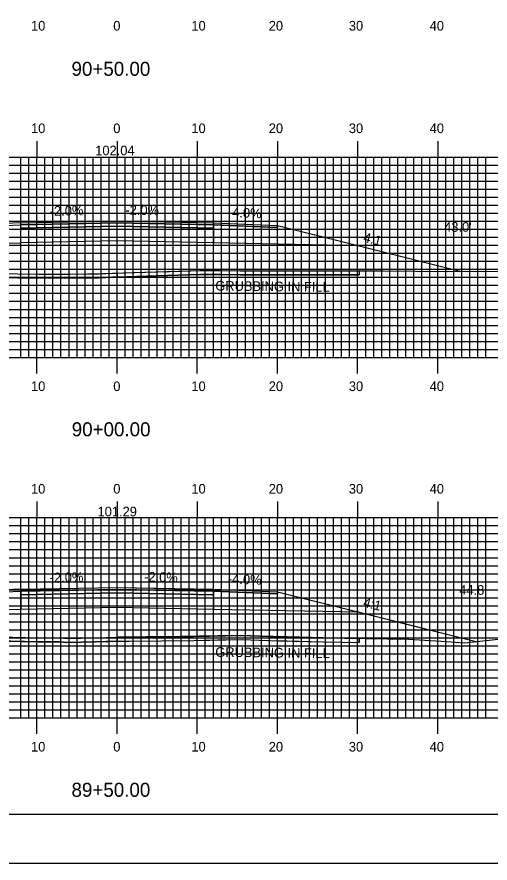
# Model space of a CAD drawing. Extents: x 1764546 to 1764889, y 442591 to 442811.
# Drawn here: x 1764698.8 to 1764757.9, y 442590.5 to 442696.2 of the extents above; entities that cross this region are included whole.
import ezdxf

# ---------------------------------------------------------------- set-up
doc = ezdxf.new("R2010")
doc.units = 0
for name, color, linetype in [('ANNOTATION', 7, 'Continuous'), ('BORDER', 7, 'Continuous'), ('D_Roadway_Centerline', 7, 'Continuous'), ('D_Roadway_Centerline_Text', 7, 'Continuous'), ('D_Roadway_Edge_Shoulder', 7, 'Continuous'), ('D_Roadway_Edge_TW', 7, 'Continuous'), ('D_Roadway_Pavement', 7, 'Continuous'), ('D_Roadway_SlopeLines', 7, 'Continuous'), ('D_Roadway_SubGrade', 7, 'Continuous'), ('D_Text_Standard', 7, 'Continuous'), ('GRUBBING IN FILL', 7, 'Continuous'), ('H_V ANNOTATION', 7, 'Continuous'), ('MAJOR', 7, 'Continuous'), ('MINOR', 7, 'Continuous'), ('PLOT BOUNDARY', 7, 'Continuous'), ('S_Roadway_Centerline', 7, 'Continuous')]:
    doc.layers.add(name, color=color, linetype=linetype)

msp = doc.modelspace()

# ---------------------------------------------------------------- linework, layer by layer
at = {"layer": 'ANNOTATION'}
msp.add_line((1764681.17, 442667.6), (1764699.34, 442667.97), dxfattribs=at)
at = {"layer": 'BORDER'}
msp.add_lwpolyline([(1764561.74, 442596.67), (1764881.74, 442596.67), (1764881.74, 442806.67), (1764561.74, 442806.67)], close=True, dxfattribs=at)
at = {"layer": 'D_Roadway_Centerline'}
msp.add_lwpolyline([(1764671.18, 442619.35), (1764675.92, 442620.54), (1764681.17, 442621.85), (1764681.18, 442621.85), (1764689.31, 442623.89), (1764691.35, 442624.4), (1764691.35, 442624.4), (1764693.28, 442624.47), (1764699.34, 442624.72), (1764699.34, 442624.72), (1764711.34, 442624.96), (1764722.68, 442624.73), (1764723.34, 442624.72), (1764731.34, 442624.4), (1764741.52, 442621.85), (1764741.52, 442621.85), (1764743.34, 442621.4), (1764749.46, 442619.87), (1764756.1, 442618.21)], dxfattribs=at)
at = {"layer": 'D_Roadway_Edge_Shoulder'}
for points in [[(1764699.34, 442670.47), (1764691.35, 442670.15), (1764691.35, 442669.9), (1764699.34, 442670.22)], [(1764723.34, 442670.47), (1764731.35, 442670.15), (1764731.35, 442669.9), (1764723.34, 442670.22)], [(1764699.34, 442624.72), (1764691.35, 442624.4), (1764691.35, 442624.15), (1764699.34, 442624.47)], [(1764723.34, 442624.72), (1764731.34, 442624.4), (1764731.34, 442624.15), (1764723.34, 442624.47)]]:
    msp.add_lwpolyline(points, close=True, dxfattribs=at)
at = {"layer": 'D_Roadway_Edge_TW'}
for points in [[(1764699.34, 442670.22), (1764699.34, 442670.47), (1764711.34, 442670.71), (1764723.34, 442670.47), (1764723.34, 442670.22), (1764711.34, 442670.46)], [(1764723.34, 442670.47), (1764723.34, 442670.47), (1764723.34, 442670.22), (1764723.34, 442670.22)], [(1764699.34, 442624.47), (1764699.34, 442624.72), (1764711.34, 442624.96), (1764723.34, 442624.72), (1764723.34, 442624.47), (1764711.34, 442624.71)], [(1764723.34, 442624.72), (1764723.34, 442624.72), (1764723.34, 442624.47), (1764723.34, 442624.47)]]:
    msp.add_lwpolyline(points, close=True, dxfattribs=at)
at = {"layer": 'D_Roadway_Pavement'}
for points in [[(1764699.34, 442669.8), (1764699.34, 442670.22), (1764711.34, 442670.46), (1764723.34, 442670.22), (1764723.34, 442669.8), (1764711.34, 442670.04)], [(1764723.34, 442670.22), (1764723.34, 442670.22), (1764723.34, 442669.8), (1764723.34, 442669.8)], [(1764699.34, 442624.05), (1764699.34, 442624.47), (1764711.34, 442624.71), (1764723.34, 442624.47), (1764723.34, 442624.05), (1764711.34, 442624.29)], [(1764723.34, 442624.47), (1764723.34, 442624.47), (1764723.34, 442624.05), (1764723.34, 442624.05)]]:
    msp.add_lwpolyline(points, close=True, dxfattribs=at)
for points in [[(1764723.34, 442670.22), (1764723.34, 442669.8)], [(1764723.34, 442670.22), (1764723.34, 442669.8)], [(1764723.34, 442670.22), (1764723.34, 442669.8)], [(1764723.34, 442624.47), (1764723.34, 442624.05)], [(1764723.34, 442624.47), (1764723.34, 442624.05)], [(1764723.34, 442624.47), (1764723.34, 442624.05)]]:
    msp.add_lwpolyline(points, dxfattribs=at)
at = {"layer": 'D_Roadway_SlopeLines'}
for points in [[(1764731.35, 442670.15), (1764741.52, 442667.6), (1764743.34, 442667.15), (1764754.3, 442664.41)], [(1764731.34, 442624.4), (1764741.52, 442621.85), (1764743.34, 442621.4), (1764756.1, 442618.21)]]:
    msp.add_lwpolyline(points, dxfattribs=at)
at = {"layer": 'D_Roadway_SubGrade'}
for points in [[(1764723.34, 442669.8), (1764723.34, 442670.22), (1764731.35, 442669.9), (1764731.35, 442670.15), (1764741.52, 442667.6), (1764723.34, 442667.97)], [(1764699.34, 442667.97), (1764699.34, 442669.8), (1764711.34, 442670.04), (1764723.34, 442669.8), (1764723.34, 442667.97), (1764711.34, 442668.21)], [(1764723.34, 442669.8), (1764723.34, 442669.8), (1764723.34, 442667.97), (1764723.34, 442667.97)], [(1764691.35, 442624.15), (1764699.34, 442624.47), (1764699.34, 442624.05), (1764699.34, 442622.22), (1764681.17, 442621.85), (1764691.35, 442624.4)], [(1764699.34, 442622.22), (1764699.34, 442624.05), (1764711.34, 442624.29), (1764723.34, 442624.05), (1764723.34, 442622.22), (1764711.34, 442622.46)], [(1764723.34, 442624.05), (1764723.34, 442624.47), (1764731.34, 442624.15), (1764731.34, 442624.4), (1764741.52, 442621.85), (1764723.34, 442622.22)], [(1764723.34, 442624.05), (1764723.34, 442624.05), (1764723.34, 442622.22), (1764723.34, 442622.22)]]:
    msp.add_lwpolyline(points, close=True, dxfattribs=at)
at = {"layer": 'GRUBBING IN FILL'}
for p, q in [((1764741.52, 442664.49), (1764741.52, 442663.99)), ((1764741.52, 442618.58), (1764741.52, 442618.08))]:
    msp.add_line(p, q, dxfattribs=at)
for points in [[(1764681.17, 442664.12), (1764685.29, 442663.94), (1764690.36, 442663.79), (1764691.23, 442663.94), (1764693, 442663.68), (1764695.53, 442663.67), (1764696.92, 442663.65), (1764698.9, 442663.62), (1764702.85, 442663.55), (1764707.64, 442663.59), (1764708.26, 442663.58), (1764710.77, 442663.67), (1764721.72, 442664.02), (1764726.7, 442663.99), (1764734.7, 442663.98), (1764741.52, 442663.99)], [(1764696.23, 442664.16), (1764698.91, 442664.12), (1764701.59, 442664.07), (1764702.85, 442664.05), (1764705.25, 442664.07), (1764707.64, 442664.09), (1764708.61, 442664.1), (1764709.5, 442664.13), (1764710.75, 442664.17), (1764711.34, 442664.19), (1764711.34, 442663.69), (1764710.77, 442663.67), (1764710.2, 442663.65), (1764706.07, 442663.57), (1764704.31, 442663.56), (1764702.85, 442663.55), (1764700.88, 442663.58), (1764697.91, 442663.63)], [(1764696.23, 442664.16), (1764698.91, 442664.12), (1764701.59, 442664.07), (1764702.85, 442664.05), (1764705.25, 442664.07), (1764707.64, 442664.09), (1764708.61, 442664.1), (1764709.5, 442664.13), (1764710.75, 442664.17), (1764711.34, 442664.19), (1764711.34, 442663.69), (1764710.77, 442663.67), (1764710.2, 442663.65), (1764706.07, 442663.57), (1764704.31, 442663.56), (1764702.85, 442663.55), (1764700.88, 442663.58), (1764697.91, 442663.63)], [(1764681.17, 442618.42), (1764692.84, 442618.36), (1764695.07, 442618.31), (1764701.49, 442618.17), (1764704.16, 442618.17), (1764705.07, 442618.09), (1764712.16, 442618.26), (1764712.83, 442618.24), (1764720.89, 442618.35), (1764726.89, 442618.46), (1764731.25, 442618.3), (1764732.55, 442618.27), (1764737.02, 442618.15), (1764741.52, 442618.08)]]:
    msp.add_lwpolyline(points, dxfattribs=at)
for points in [[(1764711.34, 442664.19), (1764713.27, 442664.25), (1764716.33, 442664.35), (1764719.39, 442664.45), (1764721.71, 442664.52), (1764724.21, 442664.51), (1764726.7, 442664.49), (1764730.16, 442664.48), (1764732.5, 442664.48), (1764734.7, 442664.48), (1764739.6, 442664.48), (1764741.52, 442664.49), (1764741.52, 442663.99), (1764738.11, 442663.98), (1764734.7, 442663.98), (1764730.7, 442663.98), (1764726.7, 442663.99), (1764724.21, 442664.01), (1764721.72, 442664.02), (1764716.24, 442663.85), (1764711.34, 442663.69)], [(1764711.34, 442664.19), (1764713.27, 442664.25), (1764716.33, 442664.35), (1764719.39, 442664.45), (1764721.71, 442664.52), (1764724.21, 442664.51), (1764726.7, 442664.49), (1764730.16, 442664.48), (1764732.5, 442664.48), (1764734.7, 442664.48), (1764739.6, 442664.48), (1764741.52, 442664.49), (1764741.52, 442663.99), (1764738.11, 442663.98), (1764734.7, 442663.98), (1764730.7, 442663.98), (1764726.7, 442663.99), (1764724.21, 442664.01), (1764721.72, 442664.02), (1764716.24, 442663.85), (1764711.34, 442663.69)], [(1764681.17, 442618.92), (1764687.04, 442618.89), (1764692.84, 442618.86), (1764698.28, 442618.74), (1764701.49, 442618.67), (1764704.18, 442618.67), (1764704.64, 442618.63), (1764705.09, 442618.59), (1764708.62, 442618.68), (1764711.34, 442618.74), (1764711.34, 442618.24), (1764708.61, 442618.18), (1764705.07, 442618.09), (1764704.16, 442618.17), (1764701.49, 442618.17), (1764692.84, 442618.36), (1764681.17, 442618.42)], [(1764681.17, 442618.92), (1764687.04, 442618.89), (1764692.84, 442618.86), (1764698.28, 442618.74), (1764701.49, 442618.67), (1764704.18, 442618.67), (1764704.64, 442618.63), (1764705.09, 442618.59), (1764708.62, 442618.68), (1764711.34, 442618.74), (1764711.34, 442618.24), (1764708.61, 442618.18), (1764705.07, 442618.09), (1764704.16, 442618.17), (1764701.49, 442618.17), (1764692.84, 442618.36), (1764681.17, 442618.42)], [(1764711.34, 442618.24), (1764712.83, 442618.24), (1764716.86, 442618.29), (1764720.89, 442618.35), (1764723.89, 442618.4), (1764726.89, 442618.46), (1764731.25, 442618.3), (1764737.02, 442618.15), (1764741.52, 442618.08), (1764741.52, 442618.58), (1764737.03, 442618.65), (1764732.56, 442618.77), (1764729.08, 442618.88), (1764726.89, 442618.96), (1764723.89, 442618.9), (1764716.86, 442618.79), (1764715.01, 442618.77), (1764713.79, 442618.75), (1764712.85, 442618.74), (1764712.43, 442618.75), (1764712.14, 442618.76), (1764711.61, 442618.75), (1764711.34, 442618.74)], [(1764711.34, 442618.24), (1764712.83, 442618.24), (1764716.86, 442618.29), (1764720.89, 442618.35), (1764723.89, 442618.4), (1764726.89, 442618.46), (1764731.25, 442618.3), (1764737.02, 442618.15), (1764741.52, 442618.08), (1764741.52, 442618.58), (1764737.03, 442618.65), (1764732.56, 442618.77), (1764729.08, 442618.88), (1764726.89, 442618.96), (1764723.89, 442618.9), (1764716.86, 442618.79), (1764715.01, 442618.77), (1764713.79, 442618.75), (1764712.85, 442618.74), (1764712.43, 442618.75), (1764712.14, 442618.76), (1764711.61, 442618.75), (1764711.34, 442618.74)]]:
    msp.add_lwpolyline(points, close=True, dxfattribs=at)
at = {"layer": 'MAJOR'}
for p, q in [((1764701.34, 442680.67), (1764701.34, 442678.67)), ((1764711.34, 442680.67), (1764711.34, 442678.67)), ((1764721.34, 442680.67), (1764721.34, 442678.67)), ((1764731.34, 442680.67), (1764731.34, 442678.67)), ((1764741.34, 442680.67), (1764741.34, 442678.67)), ((1764751.34, 442680.67), (1764751.34, 442678.67)), ((1764571.34, 442678.67), (1764851.34, 442678.67)), ((1764571.34, 442678.67), (1764851.34, 442678.67)), ((1764701.34, 442653.67), (1764701.34, 442678.67)), ((1764711.34, 442653.67), (1764711.34, 442678.67)), ((1764721.34, 442653.67), (1764721.34, 442678.67)), ((1764731.34, 442653.67), (1764731.34, 442678.67)), ((1764741.34, 442653.67), (1764741.34, 442678.67)), ((1764751.34, 442653.67), (1764751.34, 442678.67)), ((1764571.34, 442673.67), (1764851.34, 442673.67)), ((1764571.34, 442668.67), (1764851.34, 442668.67)), ((1764571.34, 442663.67), (1764851.34, 442663.67)), ((1764571.34, 442658.67), (1764851.34, 442658.67)), ((1764571.34, 442653.67), (1764851.34, 442653.67)), ((1764571.34, 442653.67), (1764851.34, 442653.67)), ((1764701.34, 442651.66), (1764701.34, 442653.67)), ((1764711.34, 442651.66), (1764711.34, 442653.67)), ((1764721.34, 442651.66), (1764721.34, 442653.67)), ((1764731.34, 442651.66), (1764731.34, 442653.67)), ((1764741.34, 442651.66), (1764741.34, 442653.67)), ((1764751.34, 442651.66), (1764751.34, 442653.67)), ((1764701.34, 442635.67), (1764701.34, 442633.67)), ((1764711.34, 442635.67), (1764711.34, 442633.67)), ((1764721.34, 442635.67), (1764721.34, 442633.67)), ((1764731.34, 442635.67), (1764731.34, 442633.67)), ((1764741.34, 442635.67), (1764741.34, 442633.67)), ((1764751.34, 442635.67), (1764751.34, 442633.67)), ((1764571.34, 442633.67), (1764851.34, 442633.67)), ((1764571.34, 442633.67), (1764851.34, 442633.67)), ((1764701.34, 442608.67), (1764701.34, 442633.67)), ((1764711.34, 442608.67), (1764711.34, 442633.67)), ((1764721.34, 442608.67), (1764721.34, 442633.67)), ((1764731.34, 442608.67), (1764731.34, 442633.67)), ((1764741.34, 442608.67), (1764741.34, 442633.67)), ((1764751.34, 442608.67), (1764751.34, 442633.67)), ((1764571.34, 442628.67), (1764851.34, 442628.67)), ((1764571.34, 442623.67), (1764851.34, 442623.67)), ((1764571.34, 442618.67), (1764851.34, 442618.67)), ((1764571.34, 442613.67), (1764851.34, 442613.67)), ((1764571.34, 442608.67), (1764851.34, 442608.67)), ((1764571.34, 442608.67), (1764851.34, 442608.67)), ((1764701.34, 442606.66), (1764701.34, 442608.67)), ((1764711.34, 442606.66), (1764711.34, 442608.67)), ((1764721.34, 442606.66), (1764721.34, 442608.67)), ((1764731.34, 442606.66), (1764731.34, 442608.67)), ((1764741.34, 442606.66), (1764741.34, 442608.67)), ((1764751.34, 442606.66), (1764751.34, 442608.67))]:
    msp.add_line(p, q, dxfattribs=at)
at = {"layer": 'MINOR'}
for p, q in [((1764699.34, 442653.67), (1764699.34, 442678.67)), ((1764700.34, 442653.67), (1764700.34, 442678.67)), ((1764702.34, 442653.67), (1764702.34, 442678.67)), ((1764703.34, 442653.67), (1764703.34, 442678.67)), ((1764704.34, 442653.67), (1764704.34, 442678.67)), ((1764705.34, 442653.67), (1764705.34, 442678.67)), ((1764706.34, 442653.67), (1764706.34, 442678.67)), ((1764707.34, 442653.67), (1764707.34, 442678.67)), ((1764708.34, 442653.67), (1764708.34, 442678.67)), ((1764709.34, 442653.67), (1764709.34, 442678.67)), ((1764710.34, 442653.67), (1764710.34, 442678.67)), ((1764712.34, 442653.67), (1764712.34, 442678.67)), ((1764713.34, 442653.67), (1764713.34, 442678.67)), ((1764714.34, 442653.67), (1764714.34, 442678.67)), ((1764715.34, 442653.67), (1764715.34, 442678.67)), ((1764716.34, 442653.67), (1764716.34, 442678.67)), ((1764717.34, 442653.67), (1764717.34, 442678.67)), ((1764718.34, 442653.67), (1764718.34, 442678.67)), ((1764719.34, 442653.67), (1764719.34, 442678.67)), ((1764720.34, 442653.67), (1764720.34, 442678.67)), ((1764722.34, 442653.67), (1764722.34, 442678.67)), ((1764723.34, 442653.67), (1764723.34, 442678.67)), ((1764724.34, 442653.67), (1764724.34, 442678.67)), ((1764725.34, 442653.67), (1764725.34, 442678.67)), ((1764726.34, 442653.67), (1764726.34, 442678.67)), ((1764727.34, 442653.67), (1764727.34, 442678.67)), ((1764728.34, 442653.67), (1764728.34, 442678.67)), ((1764729.34, 442653.67), (1764729.34, 442678.67)), ((1764730.34, 442653.67), (1764730.34, 442678.67)), ((1764732.34, 442653.67), (1764732.34, 442678.67)), ((1764733.34, 442653.67), (1764733.34, 442678.67)), ((1764734.34, 442653.67), (1764734.34, 442678.67)), ((1764735.34, 442653.67), (1764735.34, 442678.67)), ((1764736.34, 442653.67), (1764736.34, 442678.67)), ((1764737.34, 442653.67), (1764737.34, 442678.67)), ((1764738.34, 442653.67), (1764738.34, 442678.67)), ((1764739.34, 442653.67), (1764739.34, 442678.67)), ((1764740.34, 442653.67), (1764740.34, 442678.67)), ((1764742.34, 442653.67), (1764742.34, 442678.67)), ((1764743.34, 442653.67), (1764743.34, 442678.67)), ((1764744.34, 442653.67), (1764744.34, 442678.67)), ((1764745.34, 442653.67), (1764745.34, 442678.67)), ((1764746.34, 442653.67), (1764746.34, 442678.67)), ((1764747.34, 442653.67), (1764747.34, 442678.67)), ((1764748.34, 442653.67), (1764748.34, 442678.67)), ((1764749.34, 442653.67), (1764749.34, 442678.67)), ((1764750.34, 442653.67), (1764750.34, 442678.67)), ((1764752.34, 442653.67), (1764752.34, 442678.67)), ((1764753.34, 442653.67), (1764753.34, 442678.67)), ((1764754.34, 442653.67), (1764754.34, 442678.67)), ((1764755.34, 442653.67), (1764755.34, 442678.67)), ((1764756.34, 442653.67), (1764756.34, 442678.67)), ((1764757.34, 442653.67), (1764757.34, 442678.67)), ((1764571.34, 442677.67), (1764851.34, 442677.67)), ((1764571.34, 442676.67), (1764851.34, 442676.67)), ((1764571.34, 442675.67), (1764851.34, 442675.67)), ((1764571.34, 442674.67), (1764851.34, 442674.67)), ((1764571.34, 442672.67), (1764851.34, 442672.67)), ((1764571.34, 442671.67), (1764851.34, 442671.67)), ((1764571.34, 442670.67), (1764851.34, 442670.67)), ((1764571.34, 442669.67), (1764851.34, 442669.67)), ((1764571.34, 442667.67), (1764851.34, 442667.67)), ((1764571.34, 442666.67), (1764851.34, 442666.67)), ((1764571.34, 442665.67), (1764851.34, 442665.67)), ((1764571.34, 442664.67), (1764851.34, 442664.67)), ((1764571.34, 442662.67), (1764851.34, 442662.67)), ((1764571.34, 442661.67), (1764851.34, 442661.67)), ((1764571.34, 442660.67), (1764851.34, 442660.67)), ((1764571.34, 442659.67), (1764851.34, 442659.67)), ((1764571.34, 442657.67), (1764851.34, 442657.67)), ((1764571.34, 442656.67), (1764851.34, 442656.67)), ((1764571.34, 442655.67), (1764851.34, 442655.67)), ((1764571.34, 442654.67), (1764851.34, 442654.67)), ((1764699.34, 442608.67), (1764699.34, 442633.67)), ((1764700.34, 442608.67), (1764700.34, 442633.67)), ((1764702.34, 442608.67), (1764702.34, 442633.67)), ((1764703.34, 442608.67), (1764703.34, 442633.67)), ((1764704.34, 442608.67), (1764704.34, 442633.67)), ((1764705.34, 442608.67), (1764705.34, 442633.67)), ((1764706.34, 442608.67), (1764706.34, 442633.67)), ((1764707.34, 442608.67), (1764707.34, 442633.67)), ((1764708.34, 442608.67), (1764708.34, 442633.67)), ((1764709.34, 442608.67), (1764709.34, 442633.67)), ((1764710.34, 442608.67), (1764710.34, 442633.67)), ((1764712.34, 442608.67), (1764712.34, 442633.67)), ((1764713.34, 442608.67), (1764713.34, 442633.67)), ((1764714.34, 442608.67), (1764714.34, 442633.67)), ((1764715.34, 442608.67), (1764715.34, 442633.67)), ((1764716.34, 442608.67), (1764716.34, 442633.67)), ((1764717.34, 442608.67), (1764717.34, 442633.67)), ((1764718.34, 442608.67), (1764718.34, 442633.67)), ((1764719.34, 442608.67), (1764719.34, 442633.67)), ((1764720.34, 442608.67), (1764720.34, 442633.67)), ((1764722.34, 442608.67), (1764722.34, 442633.67)), ((1764723.34, 442608.67), (1764723.34, 442633.67)), ((1764724.34, 442608.67), (1764724.34, 442633.67)), ((1764725.34, 442608.67), (1764725.34, 442633.67)), ((1764726.34, 442608.67), (1764726.34, 442633.67)), ((1764727.34, 442608.67), (1764727.34, 442633.67)), ((1764728.34, 442608.67), (1764728.34, 442633.67)), ((1764729.34, 442608.67), (1764729.34, 442633.67)), ((1764730.34, 442608.67), (1764730.34, 442633.67)), ((1764732.34, 442608.67), (1764732.34, 442633.67)), ((1764733.34, 442608.67), (1764733.34, 442633.67)), ((1764734.34, 442608.67), (1764734.34, 442633.67)), ((1764735.34, 442608.67), (1764735.34, 442633.67)), ((1764736.34, 442608.67), (1764736.34, 442633.67)), ((1764737.34, 442608.67), (1764737.34, 442633.67)), ((1764738.34, 442608.67), (1764738.34, 442633.67)), ((1764739.34, 442608.67), (1764739.34, 442633.67)), ((1764740.34, 442608.67), (1764740.34, 442633.67)), ((1764742.34, 442608.67), (1764742.34, 442633.67)), ((1764743.34, 442608.67), (1764743.34, 442633.67)), ((1764744.34, 442608.67), (1764744.34, 442633.67)), ((1764745.34, 442608.67), (1764745.34, 442633.67)), ((1764746.34, 442608.67), (1764746.34, 442633.67)), ((1764747.34, 442608.67), (1764747.34, 442633.67)), ((1764748.34, 442608.67), (1764748.34, 442633.67)), ((1764749.34, 442608.67), (1764749.34, 442633.67)), ((1764750.34, 442608.67), (1764750.34, 442633.67)), ((1764752.34, 442608.67), (1764752.34, 442633.67)), ((1764753.34, 442608.67), (1764753.34, 442633.67)), ((1764754.34, 442608.67), (1764754.34, 442633.67)), ((1764755.34, 442608.67), (1764755.34, 442633.67)), ((1764756.34, 442608.67), (1764756.34, 442633.67)), ((1764757.34, 442608.67), (1764757.34, 442633.67)), ((1764571.34, 442632.67), (1764851.34, 442632.67)), ((1764571.34, 442631.67), (1764851.34, 442631.67)), ((1764571.34, 442630.67), (1764851.34, 442630.67)), ((1764571.34, 442629.67), (1764851.34, 442629.67)), ((1764571.34, 442627.67), (1764851.34, 442627.67)), ((1764571.34, 442626.67), (1764851.34, 442626.67)), ((1764571.34, 442625.67), (1764851.34, 442625.67)), ((1764571.34, 442624.67), (1764851.34, 442624.67)), ((1764571.34, 442622.67), (1764851.34, 442622.67)), ((1764571.34, 442621.67), (1764851.34, 442621.67)), ((1764571.34, 442620.67), (1764851.34, 442620.67)), ((1764571.34, 442619.67), (1764851.34, 442619.67)), ((1764571.34, 442617.67), (1764851.34, 442617.67)), ((1764571.34, 442616.67), (1764851.34, 442616.67)), ((1764571.34, 442615.67), (1764851.34, 442615.67)), ((1764571.34, 442614.67), (1764851.34, 442614.67)), ((1764571.34, 442612.67), (1764851.34, 442612.67)), ((1764571.34, 442611.67), (1764851.34, 442611.67)), ((1764571.34, 442610.67), (1764851.34, 442610.67)), ((1764571.34, 442609.67), (1764851.34, 442609.67))]:
    msp.add_line(p, q, dxfattribs=at)
at = {"layer": 'PLOT BOUNDARY'}
msp.add_lwpolyline([(1764545.56, 442590.55), (1764885.56, 442590.55), (1764885.56, 442810.55), (1764545.56, 442810.55)], close=True, dxfattribs=at)
at = {"layer": 'S_Roadway_Centerline'}
for points in [[(1764643.4, 442665.32), (1764655.3, 442665.32), (1764670.07, 442665.05), (1764672.24, 442664.98), (1764673.22, 442664.96), (1764685.31, 442664.44), (1764690.33, 442664.29), (1764691.22, 442664.44), (1764693.04, 442664.18), (1764695.53, 442664.17), (1764696.93, 442664.15), (1764698.91, 442664.12), (1764702.85, 442664.05), (1764707.64, 442664.09), (1764708.25, 442664.08), (1764710.75, 442664.17), (1764721.71, 442664.52), (1764726.7, 442664.49), (1764734.7, 442664.48), (1764744.5, 442664.49), (1764752.58, 442664.4), (1764758.91, 442664.42)], [(1764643.54, 442620.32), (1764659.22, 442619.77), (1764665.13, 442619.71), (1764677.49, 442618.99), (1764678.3, 442618.94), (1764679.95, 442618.93), (1764681.25, 442618.92), (1764692.84, 442618.86), (1764695.08, 442618.81), (1764701.49, 442618.67), (1764704.18, 442618.67), (1764705.09, 442618.59), (1764712.16, 442618.76), (1764712.84, 442618.74), (1764720.88, 442618.85), (1764726.89, 442618.96), (1764731.26, 442618.8), (1764732.56, 442618.77), (1764737.03, 442618.65), (1764747.72, 442618.48), (1764752.4, 442618.2), (1764754.65, 442618.05), (1764760.02, 442618.64)]]:
    msp.add_lwpolyline(points, dxfattribs=at)

# ---------------------------------------------------------------- texts
at = {"layer": 'ANNOTATION'}
for s, rotation, p in [('-2.0%', 1.1457, (1764702.95, 442671.34)), ('-2.0%', 358.8543, (1764712.36, 442671.49)), ('-4.0%', 357.7095, (1764725.14, 442671.2)), ('4:1', 345.9605, (1764741.97, 442668.13)), ('-2.0%', 1.1458, (1764702.95, 442625.59)), ('-2.0%', 358.8543, (1764714.7, 442625.69)), ('-4.0%', 357.7095, (1764725.14, 442625.45)), ('4:1', 345.9606, (1764741.95, 442622.57))]:
    msp.add_text(s, height=1.2, rotation=rotation, dxfattribs=at).set_placement(p)
at = {"layer": 'D_Roadway_Centerline'}
for s, p in [('C', (1764711.34, 442670.71)), ('L', (1764711.34, 442670.7)), ('C', (1764711.34, 442624.96)), ('L', (1764711.34, 442624.95))]:
    msp.add_text(s, height=0.0146, dxfattribs=at).set_placement(p)
at = {"layer": 'D_Roadway_Centerline_Text'}
for s, p in [('102.04', (1764708.61, 442678.9)), ('101.29', (1764708.9, 442633.83))]:
    msp.add_text(s, height=1.2, dxfattribs=at).set_placement(p)
at = {"layer": 'D_Text_Standard'}
for s, p in [("43.0'", (1764752.13, 442669.35)), ("44.8'", (1764754.01, 442624.04))]:
    msp.add_text(s, height=1.2, dxfattribs=at).set_placement(p)
at = {"layer": 'GRUBBING IN FILL'}
for p in [(1764723.58, 442662.02), (1764723.58, 442616.3)]:
    msp.add_text('GRUBBING IN FILL', height=1.2, rotation=359.3553, dxfattribs=at).set_placement(p)
at = {"layer": 'H_V ANNOTATION'}
for s, height, p in [('10', 1.2, (1764700.6, 442694.47)), ('0', 1.2, (1764710.86, 442694.47)), ('10', 1.2, (1764720.6, 442694.47)), ('20', 1.2, (1764730.25, 442694.47)), ('30', 1.2, (1764740.24, 442694.47)), ('40', 1.2, (1764750.32, 442694.47)), ('90+50.00', 1.75, (1764705.65, 442688.82)), ('10', 1.2, (1764700.6, 442681.67)), ('0', 1.2, (1764710.86, 442681.67)), ('10', 1.2, (1764720.6, 442681.67)), ('20', 1.2, (1764730.25, 442681.67)), ('30', 1.2, (1764740.24, 442681.67)), ('40', 1.2, (1764750.32, 442681.67)), ('10', 1.2, (1764700.6, 442649.47)), ('0', 1.2, (1764710.86, 442649.47)), ('10', 1.2, (1764720.6, 442649.47)), ('20', 1.2, (1764730.25, 442649.47)), ('30', 1.2, (1764740.24, 442649.47)), ('40', 1.2, (1764750.32, 442649.47)), ('90+00.00', 1.75, (1764705.68, 442643.82)), ('10', 1.2, (1764700.6, 442636.67)), ('0', 1.2, (1764710.86, 442636.67)), ('10', 1.2, (1764720.6, 442636.67)), ('20', 1.2, (1764730.25, 442636.67)), ('30', 1.2, (1764740.24, 442636.67)), ('40', 1.2, (1764750.32, 442636.67)), ('10', 1.2, (1764700.6, 442604.47)), ('0', 1.2, (1764710.86, 442604.47)), ('10', 1.2, (1764720.6, 442604.47)), ('20', 1.2, (1764730.25, 442604.47)), ('30', 1.2, (1764740.24, 442604.47)), ('40', 1.2, (1764750.32, 442604.47)), ('89+50.00', 1.75, (1764705.65, 442598.82))]:
    msp.add_text(s, height=height, dxfattribs=at).set_placement(p)

doc.saveas('drawing.dxf')
